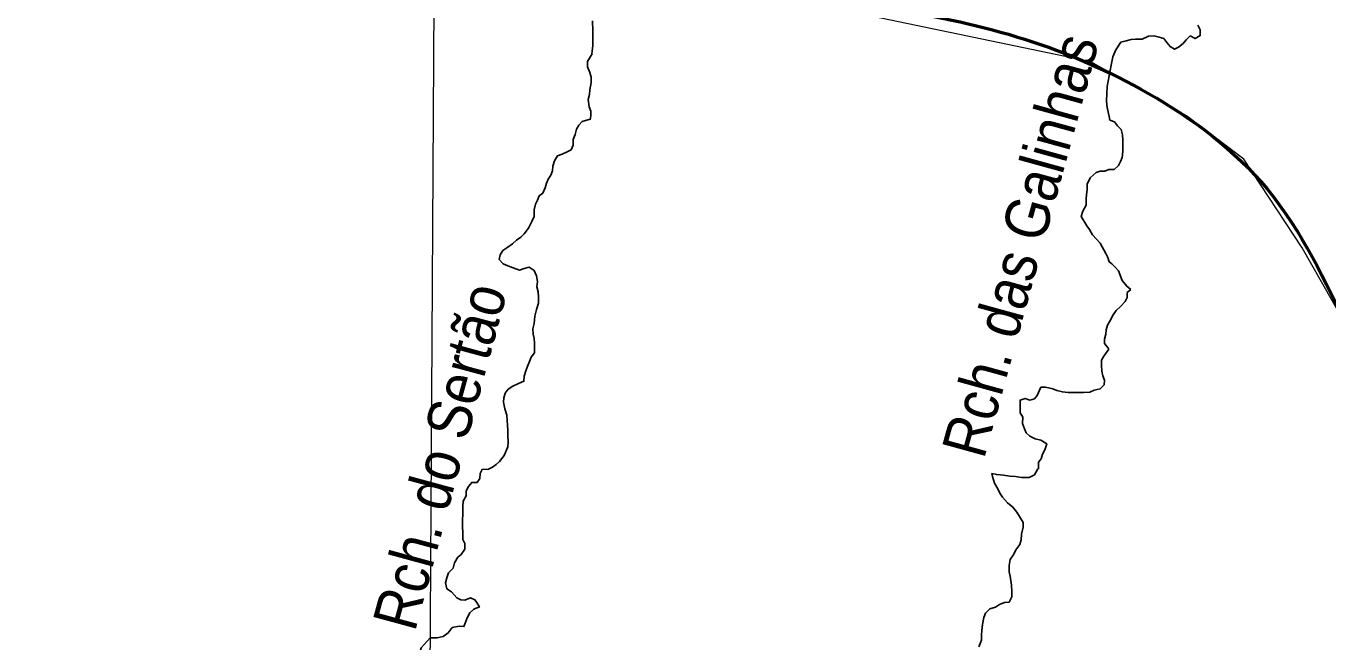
# Model space of a CAD drawing. Extents: x -1643653 to 4543381, y 1624270 to 13878484.
# Drawn here: x 714916 to 729677, y 8938163 to 8945147 of the extents above; entities that cross this region are included whole.
import ezdxf
from ezdxf.enums import TextEntityAlignment as Align

# ---------------------------------------------------------------- set-up
doc = ezdxf.new("R2010")
doc.units = 0
doc.header["$LTSCALE"] = 200
for name, color, linetype, lineweight in [('1', 7, 'Continuous', 13), ('24', 7, 'Continuous', 25), ('27', 7, 'Continuous', 13), ('28', 7, 'Continuous', 53), ('60', 7, 'Continuous', 13)]:
    doc.layers.add(name, color=color, linetype=linetype, lineweight=lineweight)
doc.layers.add('49', color=7, linetype='Continuous')

msp = doc.modelspace()

# ---------------------------------------------------------------- linework, layer by layer
at = {"layer": '1'}
msp.add_lwpolyline([(719978.9, 9023574.5), (719561.6, 8949232.2), (719215.6, 8890710.6)], dxfattribs=at)
at = {"layer": '24'}
for points in [[(728203.3, 8945156.8), (728228.4, 8945105.7), (728228, 8945039.5), (728171.8, 8945004.2), (728116, 8945035.1), (728069.9, 8944989.6), (728034.1, 8944949), (727982.9, 8944908.6), (727937, 8944883.4), (727886.3, 8944914.3), (727851, 8944960.3), (727815.8, 8945006.4), (727765, 8945022), (727704.1, 8945037.6), (727643, 8945032.9), (727571.6, 8944997.7), (727495.3, 8944998.2), (727444.4, 8944993.4), (727388.3, 8944978.4), (727327.2, 8944963.6), (727273, 8944875.7), (727239.5, 8944797.4), (727239.5, 8944797.4), (727217.1, 8944704.3), (727172.4, 8944462.1)], [(721333.1, 8944831.8), (721314, 8944802.2), (721283.1, 8944746.3), (721282.7, 8944685.2), (721307.7, 8944618.9), (721322.6, 8944567.9), (721322.1, 8944506.8), (721306.3, 8944425.4), (721305.9, 8944369.4), (721290.3, 8944313.4), (721299.9, 8944231.9), (721319.9, 8944180.8), (721319.5, 8944129.9), (721309.9, 8944083.2)], [(727172.4, 8944462.1), (727164.9, 8944294.4), (727172.4, 8944223.6), (727194.7, 8944123), (727205.5, 8944081.4), (727256.2, 8944060.7), (727291.5, 8944014.6), (727331.9, 8943973.7), (727346.8, 8943912.4), (727351.5, 8943856.4), (727351.1, 8943800.4), (727350.6, 8943729.1), (727345, 8943657.8), (727324.3, 8943612.1), (727303.7, 8943566.4), (727252.5, 8943520.9), (727191.5, 8943521.3), (727145.6, 8943501.2), (727094.7, 8943501.5), (727048.8, 8943486.5), (726982.3, 8943425.8), (726946.2, 8943354.7), (726945.7, 8943288.5), (726940.3, 8943237.7), (726934.9, 8943186.8), (726934.4, 8943115.5), (726898.3, 8943049.5), (726877.6, 8942988.5), (726942.9, 8942881.2), (726973.2, 8942840.2), (727008.3, 8942778.9), (727094.2, 8942686.7), (727159.5, 8942569.2), (727179.5, 8942523.2), (727194.4, 8942472.2)], [(721311.4, 8944090.8), (721222.4, 8944064.3), (721181.5, 8944023.8), (721155.7, 8943978.2), (721140.1, 8943917.2), (721119.3, 8943861.3), (721118.9, 8943795.1), (721098.2, 8943744.3), (721052.2, 8943719.1), (720996.1, 8943694), (720940, 8943673.9), (720909.1, 8943618.1), (720888.3, 8943557.1), (720882.9, 8943506.2), (720867.3, 8943455.4), (720836.5, 8943409.8), (720815.8, 8943364.1), (720800.2, 8943313.2), (720774.3, 8943252.3), (720733.5, 8943222), (720712.8, 8943171.2), (720692.1, 8943125.5), (720676.4, 8943064.5), (720675.9, 8942988.1), (720650.1, 8942932.2), (720613.9, 8942856.1), (720562.6, 8942790.2), (720526.8, 8942754.7), (720475.7, 8942719.4), (720429.6, 8942678.9), (720368.3, 8942633.5), (720322.3, 8942603.2), (720291.4, 8942552.5), (720280.9, 8942501.6), (720326.3, 8942450.4), (720377, 8942429.8), (720437.9, 8942403.9), (720508.9, 8942378), (720565, 8942398), (720621, 8942413), (720676.7, 8942377), (720701.7, 8942315.7), (720716.5, 8942249.4), (720706, 8942188.4), (720720.8, 8942132.3), (720725.5, 8942076.2), (720725, 8942004.9), (720704.2, 8941933.8), (720683.3, 8941857.5), (720677.7, 8941776.1), (720662, 8941715.1), (720666.7, 8941653.9), (720676.5, 8941602.9), (720681.2, 8941552), (720680.8, 8941501.1), (720680.4, 8941440), (720644.5, 8941394.3), (720623.8, 8941343.6), (720603.2, 8941297.8), (720582.4, 8941236.9), (720561.6, 8941175.9), (720561.2, 8941119.9), (720500, 8941094.8), (720433.7, 8941064.6), (720382.6, 8941029.3), (720346.7, 8940983.7), (720331.1, 8940932.9), (720330.7, 8940881.9), (720345.5, 8940805.5), (720365.3, 8940734), (720370, 8940672.9), (720374.7, 8940621.9), (720379.4, 8940565.9), (720379, 8940509.9), (720383.5, 8940428.4), (720378.1, 8940377.5), (720336.7, 8940275.9), (720285.4, 8940210), (720244.5, 8940174.6), (720203.6, 8940144.3), (720157.6, 8940124.2), (720086.4, 8940119.6), (720065.7, 8940073.9), (720060.3, 8940017.9), (720029.4, 8939972.2), (719968.4, 8939972.6), (719932.5, 8939927), (719906.7, 8939876.2), (719906.3, 8939820.2), (719870.3, 8939759.3), (719869.9, 8939703.3), (719869.3, 8939611.7), (719863.7, 8939545.5), (719863.2, 8939464), (719867.9, 8939408), (719867.3, 8939326.5), (719892.4, 8939280.5), (719892, 8939214.3), (719850.8, 8939153.5), (719810, 8939123.2), (719773.9, 8939062.3)], [(727194.4, 8942472.2), (727224.8, 8942451.7), (727260.1, 8942415.8), (727300.5, 8942369.7), (727345.5, 8942262.5), (727395.9, 8942196), (727441.4, 8942160.1), (727443.2, 8942160.1)], [(727441.4, 8942160.1), (727400.5, 8942124.7), (727400.1, 8942068.7), (727379.5, 8942023), (727328.2, 8941972.3), (727277, 8941921.7), (727241.1, 8941871), (727205, 8941800), (727179.2, 8941754.3), (727163.6, 8941703.5), (727158.2, 8941652.6), (727142.6, 8941596.7), (727142.2, 8941545.7), (727187.6, 8941489.4), (727193.7, 8941485.1)], [(727194.1, 8941484.8), (727136.1, 8941403.2), (727110.4, 8941357.5), (727110, 8941301.5), (727114.6, 8941235.3), (727124.4, 8941179.2), (727144.4, 8941133.2), (727139, 8941077.2), (727092.9, 8941031.7), (727026.7, 8941016.8), (726975.7, 8940996.8), (726904.4, 8940992.1), (726853.6, 8940992.4), (726792.5, 8940992.8), (726726.4, 8940993.2), (726665.4, 8940998.7), (726604.5, 8941014.3), (726558.9, 8941035), (726472.5, 8941050.8), (726421.7, 8941051.1), (726380.3, 8940959.7), (726349.5, 8940919.1), (726298.6, 8940904.2), (726242.8, 8940924.9), (726186.7, 8940904.8), (726186.2, 8940833.6), (726185.7, 8940762.3), (726215.9, 8940711.2), (726215.4, 8940639.9), (726235.3, 8940578.6), (726255.3, 8940532.7), (726295.8, 8940496.8), (726356.6, 8940465.9), (726422.6, 8940450.2), (726488.4, 8940409), (726467.6, 8940343), (726441.8, 8940292.2), (726426.2, 8940241.4), (726395.4, 8940200.8), (726394.9, 8940125.5)], [(725866.7, 8940074.6), (725866.7, 8940073.8), (725872.8, 8940040.7), (725897.7, 8939964.2), (725932.8, 8939897.8), (725957.9, 8939851.8), (725988.1, 8939805.8), (726043.6, 8939739.2), (726104.3, 8939693), (726149.7, 8939636.7), (726179.9, 8939585.6), (726220.1, 8939519.2), (726219.7, 8939463.2), (726203.9, 8939386.9), (726198.4, 8939320.7), (726182.8, 8939269.9), (726136.6, 8939209.1), (726115.9, 8939158.2), (726074.8, 8939097.4), (726064.2, 8939031.3), (726063.7, 8938960), (726073.5, 8938909), (726088, 8938807.1), (726092.6, 8938730.6), (726092.2, 8938674.6), (726061.2, 8938613.7), (726010.4, 8938608.9), (725954.3, 8938588.9), (725908.3, 8938558.6), (725842, 8938538.7), (725795.9, 8938488)], [(726388.5, 8940126.2), (726348.7, 8940058.5), (726287.4, 8940028.3), (726201, 8940028.9), (726134.9, 8940039.4), (726068.8, 8940044.9), (725997.7, 8940055.6), (725921.5, 8940061.1), (725866.7, 8940073.8), (725866.7, 8940073.8)], [(719773.9, 8939062.3), (719758.2, 8939001.2), (719707, 8938945.6), (719686.3, 8938889.7), (719670.6, 8938833.7), (719685.4, 8938767.4), (719741.1, 8938731.5), (719801.7, 8938664.9), (719844, 8938640.7), (719890.2, 8938638.6), (719890.2, 8938638.6)], [(720060.8, 8938559.8), (720055.8, 8938559.8), (719994.6, 8938534.7), (719948.5, 8938494.2), (719922.7, 8938443.5), (719881.3, 8938336.8), (719825.4, 8938342.2), (719749, 8938327.4), (719702.8, 8938266.6), (719646.6, 8938226.2), (719575.3, 8938211.3), (719495.9, 8938211.8)], [(719890.2, 8938638.6), (719953.8, 8938664.2), (720004.3, 8938640.4), (720024.2, 8938614.6), (720058.9, 8938563), (720061.4, 8938559.7)], [(725795.9, 8938488), (725775.3, 8938442.3), (725759.4, 8938360.9), (725753.9, 8938294.8), (725748.4, 8938238.8), (725748, 8938182.8), (725717, 8938106.6)], [(719495.9, 8938211.8), (719394.7, 8938096.4), (719328.4, 8937863.4), (719342.1, 8937802.6), (719401.1, 8937732.2), (719437, 8937644.3), (719483.8, 8937567.5), (719487.5, 8937545.9), (719449.3, 8937492.5), (719434.6, 8937455.6), (719420.2, 8937279.4), (719367.4, 8937201.3), (719297.2, 8937190.5), (719130.2, 8937185.6)]]:
    msp.add_lwpolyline(points, dxfattribs=at)
msp.add_spline([(721338.8, 8945205.7), (721343, 8945051.6), (721343, 8944957), (721332, 8944830.1)], degree=3, dxfattribs=at)
at = {"layer": '27'}
msp.add_lwpolyline([(739888.1, 8915825.1), (740072.3, 8917875.9), (737976.5, 8917968.1), (737953.4, 8923890.1), (738068.6, 8925272.7), (738224.4, 8926341.3), (739385.9, 8927129), (738750.9, 8927828.4), (738115.9, 8928527.7), (730092.7, 8935013.9), (730302.4, 8935656.6), (729966.7, 8935956.1), (730039.7, 8936358), (730463, 8936540.7), (731163.7, 8937242.1), (731798.6, 8937424.7), (731798.6, 8937424.7), (731773.1, 8938151.7), (731651.2, 8938643.9), (729383.2, 8942632.6), (728721.7, 8943637.1), (728072.1, 8944130.5), (726986.6, 8944741.7), (723300.7, 8945510.9)], dxfattribs=at)
at = {"layer": '28'}
msp.add_spline([(723248, 8945520.1), (726235.5, 8944998.5), (727640.7, 8944383.3), (728987.4, 8943299.6), (729924.3, 8941688.6), (731836.5, 8938317.2)], degree=3, dxfattribs=at)
at = {"layer": '60', "lineweight": 25}
msp.add_spline([(814781, 9009175.5), (814787.2, 9009173.4), (814796.9, 9009173.4), (814799.4, 9009172.4), (814805.1, 9009174.5), (814805.6, 9009176.5), (814811.7, 9009179.5), (814811.7, 9009179.5), (814801.5, 9009181), (814790.7, 9009181.5), (814784.1, 9009183.1), (814777.4, 9009185.1), (814778.4, 9009175.5)], degree=3, dxfattribs=at)

# ---------------------------------------------------------------- texts
at = {"layer": '49', "width": 0.9}
for s, rotation, p in [('Rch. das Galinhas', 74.592, (726429.3, 8942595.9)), ('Rch. do Sertão', 74.808, (719849.9, 8940205))]:
    msp.add_text(s, height=500, rotation=rotation, dxfattribs=at).set_placement(p, align=Align.CENTER)

doc.saveas('drawing.dxf')
